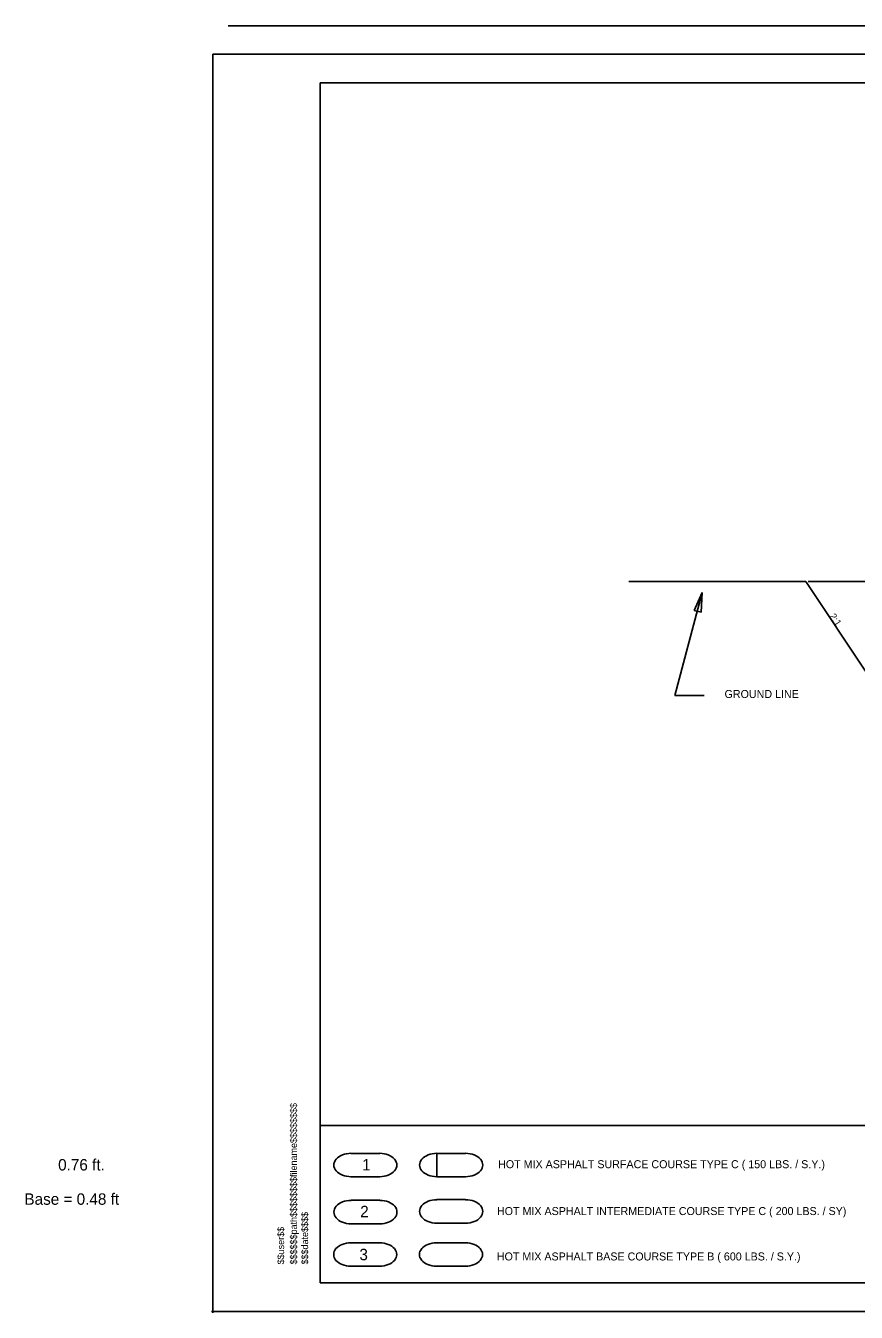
# Model space of a CAD drawing. Extents: x -9123 to -7163, y 44168 to 46468.
# Drawn here: x -9123 to -8396, y 45342 to 46468 of the extents above; entities that cross this region are included whole.
import ezdxf

# ---------------------------------------------------------------- set-up
doc = ezdxf.new("R2010")
doc.units = 0
for name, color, linetype in [('RD_SHT_Bndy', 7, 'Continuous'), ('RD_SHT_ID', 7, 'Continuous'), ('RD_SHT_IplotShp', 7, 'Continuous'), ('RD_SHT_Snap', 7, 'Continuous'), ('RD_TX_TypSect', 7, 'Continuous'), ('RD_XS_PaveOvlay', 7, 'Continuous')]:
    doc.layers.add(name, color=color, linetype=linetype)

msp = doc.modelspace()

# ---------------------------------------------------------------- linework, layer by layer
at = {"layer": 'RD_SHT_Bndy'}
for p, q in [((-8945.7, 46468), (-7185.7, 46468)), ((-8945.7, 46443), (-7185.7, 46443)), ((-7190.2, 46418), (-8865.2, 46418)), ((-8865.2, 46418), (-8865.2, 45368)), ((-8865.2, 45368), (-7190.2, 45368)), ((-8945.7, 45343), (-7185.7, 45343))]:
    msp.add_line(p, q, dxfattribs=at)
at = {"layer": 'RD_SHT_IplotShp'}
msp.add_lwpolyline([(-8959.2, 46443), (-7163.2, 46443), (-7163.2, 45343), (-8959.2, 45343)], close=True, dxfattribs=at)
at = {"layer": 'RD_SHT_Snap'}
msp.add_line((-8959.2, 46443), (-8959.2, 45343), dxfattribs=at)
msp.add_circle((-8959.2, 45343), 0.607, dxfattribs=at)
at = {"layer": 'RD_TX_TypSect'}
for p, q in [((-8594.9, 45981.6), (-8440.8, 45981.6)), ((-8550.9, 45981.6), (-8440.1, 45981.6)), ((-8386.7, 45901.5), (-8440.1, 45981.6)), ((-8438.1, 45981.6), (-8110.1, 45981.6)), ((-8554.7, 45882), (-8530.7, 45972)), ((-8537.9, 45956.4), (-8530.7, 45972)), ((-8530.7, 45972), (-8531.8, 45954.8)), ((-8531.8, 45954.8), (-8537.9, 45956.4)), ((-8554.7, 45882), (-8529, 45882)), ((-8838.2, 45481.4), (-8813, 45481.4)), ((-8763.1, 45481.4), (-8737.8, 45481.4)), ((-8763.1, 45481.4), (-8763.1, 45460.9)), ((-8737.8, 45481.4), (-8763.1, 45481.4)), ((-8763.1, 45481.4), (-8763.1, 45460.9)), ((-8813, 45460.9), (-8838.2, 45460.9)), ((-8737.8, 45460.9), (-8763.1, 45460.9)), ((-8763.1, 45460.9), (-8737.8, 45460.9)), ((-8763.1, 45440.9), (-8737.8, 45440.9)), ((-8838.1, 45440.3), (-8812.9, 45440.3)), ((-8812.9, 45419.7), (-8838.1, 45419.7)), ((-8737.8, 45420.3), (-8763.1, 45420.3)), ((-8838.3, 45403.2), (-8813.1, 45403.2)), ((-8763.3, 45403.2), (-8738, 45403.2)), ((-8732.3, 45402.5), (-8732.4, 45402.7)), ((-8813.1, 45382.6), (-8838.3, 45382.6)), ((-8738, 45382.6), (-8763.3, 45382.6))]:
    msp.add_line(p, q, dxfattribs=at)
msp.add_lwpolyline([(-8865.2, 45368), (-8379, 45368), (-8379, 45505.7), (-8865.2, 45505.7)], close=True, dxfattribs=at)
for points in [[(-8737.8, 45440.9), (-8763.1, 45440.9)], [(-8763.1, 45420.3), (-8737.8, 45420.3)], [(-8739.5, 45403), (-8739.6, 45403.2)], [(-8739.4, 45403.2), (-8739.5, 45403)]]:
    msp.add_lwpolyline(points, dxfattribs=at)
for centre, start_param, end_param in [((-8838.2, 45471.2), 1.570796, 4.712389), ((-8813, 45471.2), 4.712389, 7.853982), ((-8763.1, 45471.2), 1.570796, 4.712389), ((-8763.1, 45471.2), 1.570796, 4.712389), ((-8737.8, 45471.2), 4.712389, 7.853982), ((-8737.8, 45471.2), 4.712389, 7.853982), ((-8763.1, 45430.6), 1.570796, 4.712389), ((-8763.1, 45430.6), 1.570796, 4.712389), ((-8737.8, 45430.6), 4.712389, 7.853982), ((-8737.8, 45430.6), 4.712389, 7.853982), ((-8838.1, 45430), 1.570796, 4.712389), ((-8812.9, 45430), 4.712389, 7.853982), ((-8838.3, 45392.9), 1.570796, 4.712389), ((-8813.1, 45392.9), 4.712389, 7.853982), ((-8763.3, 45392.9), 1.570796, 4.712389), ((-8738, 45392.9), 4.712389, 7.853982)]:
    msp.add_ellipse(centre, major_axis=(15, 0), ratio=0.682631, start_param=start_param, end_param=end_param, dxfattribs=at)
at = {"layer": 'RD_XS_PaveOvlay'}
for p, q in [((-8738, 45403.2), (-8763.3, 45403.2)), ((-8763.3, 45382.6), (-8738, 45382.6))]:
    msp.add_line(p, q, dxfattribs=at)
for centre, start_param, end_param in [((-8763.3, 45392.9), 1.570796, 4.712389), ((-8738, 45392.9), 4.712389, 7.853982)]:
    msp.add_ellipse(centre, major_axis=(15, 0), ratio=0.682631, start_param=start_param, end_param=end_param, dxfattribs=at)

# ---------------------------------------------------------------- texts
at = {"layer": 'RD_SHT_ID'}
for s, p in [('$$$$$$path$$$$$$$$filename$$$$$$$$', (-8885.5, 45384.2)), ('$$$date$$$$', (-8875.7, 45384.2)), ('$$user$$', (-8896.7, 45384.3))]:
    msp.add_text(s, height=5.88, rotation=90, dxfattribs=at).set_placement(p)
at = {"layer": 'RD_TX_TypSect'}
msp.add_text('2:1', height=6, rotation=304.1064, dxfattribs=at).set_placement((-8419.6, 45951.3))
for s, height, p in [('GROUND LINE', 7, (-8511.2, 45879.8)), ('0.76 ft.', 10, (-9094.5, 45466.4)), ('1', 10, (-8828.5, 45466.4)), ('HOT MIX ASPHALT SURFACE COURSE TYPE C ( 150 LBS. / S.Y.)', 7, (-8709.4, 45468.4)), ('Base = 0.48 ft', 10, (-9124, 45436.4)), ('2', 10, (-8830.1, 45425.5)), ('HOT MIX ASPHALT INTERMEDIATE COURSE TYPE C ( 200 LBS. / SY)', 7, (-8710.4, 45427.4)), ('3', 10, (-8830.8, 45387.9)), ('HOT MIX ASPHALT BASE COURSE TYPE B ( 600 LBS. / S.Y.)', 7, (-8710.5, 45387.7))]:
    msp.add_text(s, height=height, dxfattribs=at).set_placement(p)

doc.saveas('drawing.dxf')
